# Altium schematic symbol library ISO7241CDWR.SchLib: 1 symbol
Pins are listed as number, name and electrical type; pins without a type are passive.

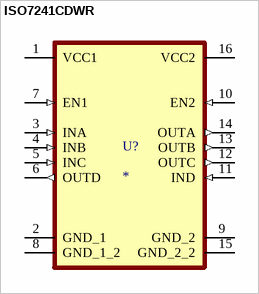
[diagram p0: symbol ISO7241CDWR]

## ISO7241CDWR
designator U?
MP: ISO7241CDWR
footprint ISO7241CDWR
pins: 1 VCC1 (power), 2 GND_1 (power), 3 INA (in), 4 INB (in), 5 INC (in), 6 OUTD (out), 7 EN1 (in), 8 GND_1_2 (power), 9 GND_2 (power), 10 EN2 (in), 11 IND (in), 12 OUTC (out), 13 OUTB (out), 14 OUTA (out), 15 GND_2_2 (power), 16 VCC2 (power)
